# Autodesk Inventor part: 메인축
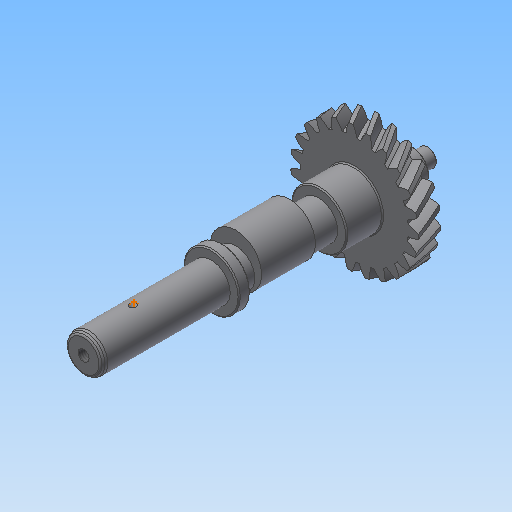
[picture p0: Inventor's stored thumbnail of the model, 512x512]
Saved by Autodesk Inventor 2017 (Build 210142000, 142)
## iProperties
Created: 2016-12
Part Number: 메인축
Material: 강철, 탄소
Document SubType Name: Modeling
Designer: mduedu
Categories: <?xml version="1.0" encoding="UTF-16"?> <MemberInstance><Categories><FamilyTemplate><FamilyTemplateParameter ValueType="xs:double" Id="1" ObjectReferenceKey="da
Density: 7.87 g/cm^3
Appearance: 기본값
Mass: 488.971 g
Surface Area: 171.637 cm^2
Volume: 62.131 cm^3
CustomPartVersion: 1
Author: mduedu
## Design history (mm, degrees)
sketch "Sketch1"
  geometry: C1 r 28.558 at (0, 0)
  constraints: 1 centre point
  dimensions: "d0" = 57.11622 diameter of C1 (= da_da)
extrude "Extrusion1" new body sketch "Sketch1" distance "d1" = 10 (= da_b); taper "d2" = 0 deg
workplane "Work Plane2"
sketch "Sketch2"
  geometry: C1 r 28.558 at (0, 0) reference; C2 r 26.558 at (0, 0)
  constraints: 1 centre point, 1 coincident
  dimensions: "d3" = 53.11622 diameter of C2 (= da_dw)
feature "피치 지름" sketch "Sketch2" dims "d4" = 10, "d5" = 0
workplane "Work Plane8"
workplane "Work Plane9"
feature "스퍼 기어" dims "d72" = 0, "da_b" = 10, "da_d" = 53.11622, "da_aw" = 43.87862, "da_da" = 57.11622, "da_df" = 48.11622, "da_dw" = 53.11622, angle "da_beta" = 30 deg, "da_lefttooth" = 10, "da_righttooth" = 0
sketch "스케치3"
  geometry: C1 r 12.5 at (0, 0); 1 further point
  constraints: 1 centre point, 1 coincident
  dimensions: "d49" = 25 diameter of C1
extrude "돌출2" join sketch "스케치3" distance "d50" = 16; taper "d51" = 0 deg
sketch "스케치4"
  geometry: C1 r 8.5 at (0, 0); 1 further point
  constraints: 1 centre point, 1 coincident
  dimensions: "d52" = 17 diameter of C1
extrude "돌출3" join sketch "스케치4" distance "d53" = 105; taper "d54" = 0 deg
sketch "스케치5"
  geometry: C1 r 7.5 at (0, 0); 1 further point
  constraints: 1 centre point, 1 coincident
  dimensions: "d55" = 15 diameter of C1
extrude "돌출4" join sketch "스케치5" distance "d56" = 16; taper "d57" = 0 deg
sketch "스케치6"
  geometry: C1 r 4 at (0, 0); 1 further point
  constraints: 1 centre point, 1 coincident
  dimensions: "d58" = 8 diameter of C1
extrude "돌출5" join sketch "스케치6" distance "d59" = 7; taper "d60" = 0 deg
chamfer "모따기1" distance "d61" = 0.5; stored, may be unused: second distance "d62" = 2, angle "d63" = 45 deg
fillet "모깎기1" dims "d64" = 0.5
node "작업 평면11"
sketch "스케치7"
  geometry: C1 r 11.5 at (0, 3); C2 r 8.5 at (0, 0) reference; 1 further point
  constraints: 1 centre point, 1 tangent, 1 vertical alignment
  dimensions: "d66" = 3 distance of point (0, 0) C1.centre; "d67" = 23 diameter of C1 (derived)
extrude "돌출6" join sketch "스케치7" stored distance "d68" = 24; taper "d69" = 0 deg
node "작업 평면12"
sketch "스케치8"
  geometry: C1 r 12.5 at (0, 0) reference; 1 further point
extrude "돌출7" join sketch "스케치8" distance "d71" = 5; taper "d72" = 0 deg
chamfer "모따기2" distance "d73" = 0.5; stored, may be unused: second distance "d74" = 2, angle "d75" = 45 deg
node "작업 평면13"
sketch "스케치9" dims "d81" = 18
  geometry: L1 (2.5, 95.5)-(-2.5, 95.5); L2 (-2.5, 95.5)-(-2.5, 82.5); L3 (-2.5, 82.5)-(2.5, 82.5); L4 (2.5, 82.5)-(2.5, 95.5); L5 (8.5, 105)-(-8.5, 105) reference; 3 further points
  constraints: 8 end point, 2 horizontal alignment, 2 midpoint, 2 parallel, 1 horizontal, 1 perpendicular, 1 vertical alignment, 4 other
  dimensions: "d79" = 5 distance between parallel lines of L2 L4; "d98" = 7 dimension on L5
extrude "돌출8" cut sketch "스케치9" distance "d83" = 3; taper "d84" = 0 deg
sketch "스케치10"
  geometry: L1 (-8.5, 74)-(-8.5, 131) reference; L2 (8.5, 74)-(8.5, 131) reference; L3 (8.5, 109)-(-8.5, 109); L4 (8.5, 109)-(7, 109); L5 (7, 109)-(8.5, 107.5); L6 (8.5, 107.5)-(8.5, 109); L7 (8.5, 131)-(-8.5, 131) reference; 1 further point
  constraints: 8 end point, 4 point on line, 2 perpendicular
  dimensions: "d86" = 45 deg angle of L5 L4; "d87" = 3 diameter of L5.end L3; "d99" = 22 distance between parallel lines of L7 L3
revolve "회전1" stored, may be unused: angle "d88" = 90 deg
sketch "스케치11"
  geometry: L1 (-8.5, 74)-(-8.5, 131) reference; L2 (-40.7, 131)-(40.7, 131) reference; L3 (-7.45, 131)-(-8.5, 129.181); L4 (0, 131)-(0, 0); L5 (-8.5, 129.181)-(-8.5, 131); L6 (-7.45, 131)-(-8.5, 131)
  constraints: 8 end point, 2 perpendicular, 2 point on line, 1 collinear, 1 midpoint
  dimensions: "d100" = 30 deg angle of L1 L3; "d101" = 14.9 diameter of L3.start L4
revolve "회전2" sketch "스케치11" stored, may be unused: angle "d102" = 90 deg
fillet "모깎기2" dims "d103" = 2, "d113" = 1
hole "구멍2" diameter "d106" = 4.917; stored, may be unused: countersink angle "d110" = 90 deg, drill point angle "d112" = 118 deg; dims "d104" = 10, "d105" = 10, "d107" = 10, "d108" = 4, "d109" = 2, "d111" = 12
node "작업점1"
body "Solid1"
body "Srf1"
node "참조1"
other parameters: "d16" = 43.87862 (= da_aw), "d17" = 0, "d34" = 1.36591 (computed from da_z), "d39" = 0, "d41" = 0, "d43" = 43.87862 (= da_aw), "d46" = 43.87862 (= da_aw), "d47" = 0, "d48" = 0, "d65" = 25, "d70" = 48
